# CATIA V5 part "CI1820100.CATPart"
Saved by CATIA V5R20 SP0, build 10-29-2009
Part number: CI1820100
Bounding box of the stored display mesh (mm): x -9 to 29, y -15.149 to 130, z -13.548 to 31.957
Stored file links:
  C:\Users\Raffaele\Desktop\3D X SITO CF\BOLEX\19-INCLINED ASSEMBLY REF_CI\CI1820100.CATPart

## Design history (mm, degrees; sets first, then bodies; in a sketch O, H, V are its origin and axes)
Set1
  DatumSurface1 to DatumSurface16 "MANIFOLD_SOLID_BREP #385"
  DatumSurface17 to DatumSurface39 "MANIFOLD_SOLID_BREP #1114"
Body1 (main body)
